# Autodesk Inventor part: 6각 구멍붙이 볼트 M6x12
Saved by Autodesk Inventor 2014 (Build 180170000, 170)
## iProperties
Created: 2025-09
Part Number: 6각 구멍붙이 볼트 M6x12
Material: 일반
Document SubType Name: Modeling
Designer: dg
Density: 1 g/cm^3
Appearance: 기본값
Author: dg
Author: jhkim
Description: 6각머리 태핑 나사
Creation Date: 2025-09-02
Sending System: Autodesk Inventor 2026
Preprocessor: ST-DEVELOPER v20.1
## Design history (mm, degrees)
node "6각 구멍붙이 볼트 M6x121"
body "Solid1"
node "기준1"
